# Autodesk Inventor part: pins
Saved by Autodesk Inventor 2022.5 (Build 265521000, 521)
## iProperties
Created: 2024-12
Part Number: pins
Material: Generic
Document SubType Name: Modeling
Designer: AdminForWorker
Density: 1 g/cm^3
Appearance: Default
Title: pins
Author: AdminForWorker
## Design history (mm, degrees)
feature "Body1"
feature "Body2"
feature "Body3"
feature "Body4"
body "Solid1"
body "Solid2"
body "Solid3"
body "Solid4"
